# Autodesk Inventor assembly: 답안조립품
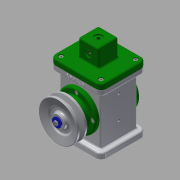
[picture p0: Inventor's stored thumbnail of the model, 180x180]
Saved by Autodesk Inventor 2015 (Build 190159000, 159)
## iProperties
Created: 2017-08
Part Number: 답안조립품
Document SubType Name: Assembly
Designer: Administrator
Author: Administrator
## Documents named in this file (18)
- C:\Users\Administrator\Desktop\470807V1005\답안조립품.iam
- C:\Users\Administrator\Desktop\470807V1005\본체.ipt
- C:\Users\Administrator\Desktop\470807V1005\E-링.ipt
- C:\Users\Administrator\Desktop\470807V1005\V-벨트풀리.ipt
- C:\Users\Administrator\Desktop\470807V1005\덮개.ipt
- C:\Users\Administrator\Desktop\470807V1005\뒤커버.ipt
- C:\Users\Administrator\Desktop\470807V1005\링크.ipt
- C:\Users\Administrator\Desktop\470807V1005\베어링 17 x 40 x 12.ipt
- C:\Users\Administrator\Desktop\470807V1005\볼트 M4 x 8.ipt
- C:\Users\Administrator\Desktop\470807V1005\볼트 M4 x 10.ipt
- C:\Users\Administrator\Desktop\470807V1005\슬라이더.ipt
- C:\Users\Administrator\Desktop\470807V1005\앞커버.ipt
- C:\Users\Administrator\Desktop\470807V1005\오일 실 17 30 8.ipt
- C:\Users\Administrator\Desktop\470807V1005\와셔 4x16.ipt
- C:\Users\Administrator\Desktop\470807V1005\클레비스 핀 6 x 22.ipt
- 클레비스 핀 6 x 22.ipt
- C:\Users\Administrator\Desktop\470807V1005\키 4 x 4 x 12.ipt
- C:\Users\Administrator\Desktop\470807V1005\편심축.ipt
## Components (2 placed, 2 different names)
1. E-링:1
2. V-벨트풀리:1
